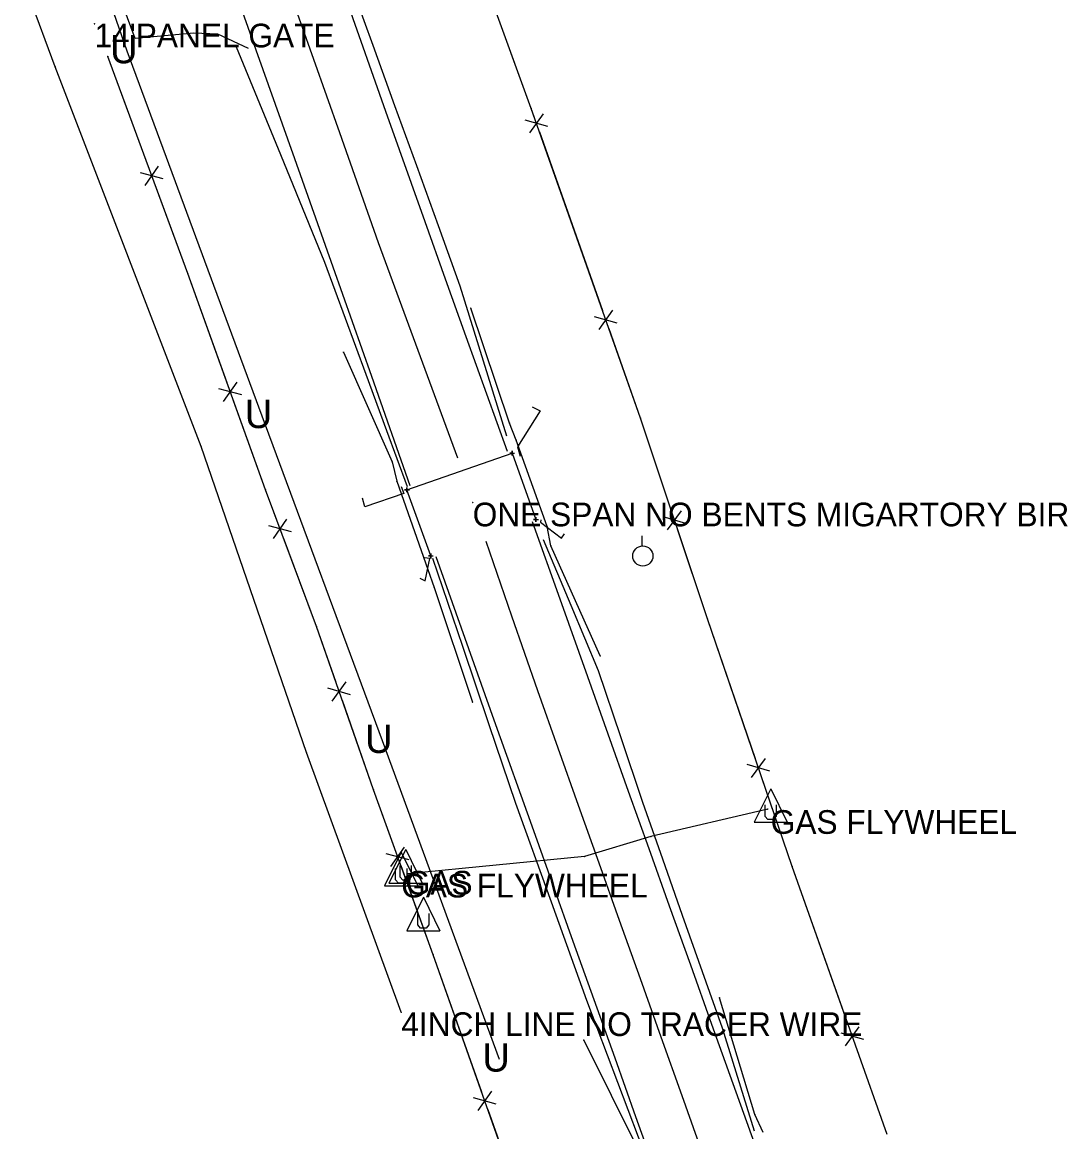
# Model space of a CAD drawing. Extents: x 1050807 to 1053552, y 395828 to 398415.
# Drawn here: x 1052358.5 to 1052579.3, y 396632.8 to 396867.1 of the extents above; entities that cross this region are included whole.
import ezdxf

# ---------------------------------------------------------------- set-up
doc = ezdxf.new("R2010")
doc.units = 0
for name, color, linetype in [('Default', 7, 'Continuous'), ('S_BRIDGE', 7, 'Continuous'), ('S_DRIVEWAY', 7, 'Continuous'), ('S_EDGE_CONCRETE', 7, 'Continuous'), ('S_EDGE_PAVEMENT', 7, 'Continuous'), ('S_FENCE', 7, 'Continuous'), ('S_GAS_UTILITIES', 7, 'Continuous'), ('S_GUARDRAIL', 7, 'Continuous'), ('S_MSC_PT_SYM', 7, 'Continuous'), ('S_PAVEMENT_CROWN', 7, 'Continuous'), ('S_RDW_PT_SYM', 7, 'Continuous'), ('S_SHOULDER', 7, 'Continuous'), ('S_STR_PT_SYM', 7, 'Continuous'), ('S_SURVEY_TEXT_ANNOT', 7, 'Continuous'), ('S_UNDERGROUND_CABLE', 7, 'Continuous'), ('S_UTILITY_POLE', 7, 'Continuous'), ('S_UTILITY_POLE_ANNOT', 7, 'Continuous'), ('S_UTL_PT_SYM', 7, 'Continuous'), ('S_WATER_UTILITIES', 7, 'Continuous'), ('S_WATER_UTILITIES_ANNOT', 7, 'Continuous')]:
    doc.layers.add(name, color=color, linetype=linetype)

msp = doc.modelspace()

# ---------------------------------------------------------------- linework, layer by layer
at = {"layer": 'S_BRIDGE'}
for p, q in [((1052439.78, 396768.34), (1052462.01, 396776.09)), ((1052462.01, 396776.09), (1052467.01, 396762.11)), ((1052444.83, 396754.39), (1052439.78, 396768.34))]:
    msp.add_line(p, q, dxfattribs=at)
at = {"layer": 'S_DRIVEWAY'}
msp.add_lwpolyline([(1052406.35, 396861.47), (1052399.84, 396864.53), (1052394.81, 396864.76), (1052382.42, 396863.64), (1052378.24, 396874.85), (1052383.77, 396877.82), (1052391.56, 396884.45), (1052395.94, 396888.79)], dxfattribs=at)
at = {"layer": 'S_EDGE_CONCRETE'}
for points in [[(1052466.22, 396785.86), (1052467.92, 396785.05), (1052463.09, 396777.45), (1052463.66, 396775.47)], [(1052438.55, 396769.02), (1052439.14, 396767.59), (1052430.89, 396764.79), (1052430.41, 396766.58)], [(1052468.01, 396762.05), (1052468, 396761.53), (1052472.4, 396758.14), (1052473.05, 396759.08)], [(1052442.5, 396749.68), (1052443.6, 396749.14), (1052444.62, 396753.83), (1052443.49, 396753.98)]]:
    msp.add_lwpolyline(points, dxfattribs=at)
at = {"layer": 'S_EDGE_PAVEMENT'}
for points in [[(1052460.97, 396776.43), (1052456.62, 396788.55), (1052452.28, 396800.67), (1052447.93, 396812.79), (1052443.59, 396824.9), (1052435.34, 396848.24), (1052427.09, 396871.57), (1052422.4, 396884.33), (1052417.71, 396897.09), (1052413.02, 396909.86), (1052408.33, 396922.62), (1052403.21, 396936.38), (1052398.09, 396950.14), (1052392.97, 396963.89), (1052387.86, 396977.65)], [(1052440.47, 396769.17), (1052432.33, 396792.24), (1052424.18, 396815.32), (1052416.08, 396838.25), (1052407.97, 396861.18), (1052400.04, 396883.52), (1052392.11, 396905.86), (1052386.39, 396922.34), (1052380.67, 396938.83), (1052374.95, 396955.32), (1052369.23, 396971.8)], [(1052513.12, 396630.45), (1052508.63, 396642.96), (1052504.15, 396655.48), (1052499.67, 396667.99), (1052495.19, 396680.5), (1052490.88, 396692.59), (1052486.56, 396704.68), (1052482.25, 396716.78), (1052477.94, 396728.87), (1052472.12, 396745.25), (1052466.29, 396761.63)], [(1052492.52, 396623.71), (1052488.11, 396636.03), (1052483.7, 396648.36), (1052479.29, 396660.69), (1052474.88, 396673.01), (1052466.54, 396696.37), (1052458.19, 396719.73), (1052452.07, 396736.99), (1052445.94, 396754.24)]]:
    msp.add_lwpolyline(points, dxfattribs=at)
at = {"layer": 'S_FENCE'}
for p, q in [((1052466.02, 396848.87), (1052444.41, 396908.05)), ((1052393.51, 396813.99), (1052376.64, 396859.85)), ((1052465.68, 396843.67), (1052468.59, 396847.74)), ((1052465.68, 396843.67), (1052468.59, 396847.74)), ((1052489.1, 396783.48), (1052466.02, 396848.87)), ((1052469.54, 396845.03), (1052464.73, 396846.37)), ((1052469.54, 396845.03), (1052464.73, 396846.37)), ((1052384.49, 396832.58), (1052387.34, 396836.69)), ((1052384.49, 396832.58), (1052387.34, 396836.69)), ((1052388.33, 396834), (1052383.5, 396835.28)), ((1052388.33, 396834), (1052383.5, 396835.28)), ((1052409.94, 396768.35), (1052393.51, 396813.99)), ((1052480.32, 396802.19), (1052483.23, 396806.26)), ((1052480.32, 396802.19), (1052483.23, 396806.26)), ((1052484.18, 396803.55), (1052479.37, 396804.89)), ((1052484.18, 396803.55), (1052479.37, 396804.89)), ((1052404.9, 396788.39), (1052400.08, 396789.7)), ((1052404.9, 396788.39), (1052400.08, 396789.7)), ((1052401.05, 396787), (1052403.93, 396791.09)), ((1052401.05, 396787), (1052403.93, 396791.09)), ((1052503.21, 396741.1), (1052489.1, 396783.48)), ((1052420.68, 396739.54), (1052409.94, 396768.35)), ((1052494.78, 396759.94), (1052497.76, 396763.95)), ((1052494.78, 396759.94), (1052497.76, 396763.95)), ((1052411.59, 396758.05), (1052414.43, 396762.16)), ((1052411.59, 396758.05), (1052414.43, 396762.16)), ((1052498.66, 396761.23), (1052493.87, 396762.66)), ((1052498.66, 396761.23), (1052493.87, 396762.66)), ((1052415.43, 396759.48), (1052410.59, 396760.73)), ((1052415.43, 396759.48), (1052410.59, 396760.73)), ((1052521.09, 396688.84), (1052503.21, 396741.1)), ((1052432.72, 396705.02), (1052420.68, 396739.54)), ((1052427.88, 396725.1), (1052423.07, 396726.46)), ((1052427.88, 396725.1), (1052423.07, 396726.46)), ((1052424.02, 396723.75), (1052426.94, 396727.81)), ((1052424.02, 396723.75), (1052426.94, 396727.81)), ((1052516.37, 396708.96), (1052511.57, 396710.35)), ((1052516.37, 396708.96), (1052511.57, 396710.35)), ((1052512.5, 396707.63), (1052515.44, 396711.67)), ((1052512.5, 396707.63), (1052515.44, 396711.67)), ((1052445.33, 396670.2), (1052432.72, 396705.02)), ((1052440.25, 396690.24), (1052435.42, 396691.54)), ((1052440.25, 396690.24), (1052435.42, 396691.54)), ((1052436.4, 396688.84), (1052439.28, 396692.93)), ((1052436.4, 396688.84), (1052439.28, 396692.93)), ((1052541.18, 396632.28), (1052521.09, 396688.84)), ((1052463.57, 396618.62), (1052445.33, 396670.2)), ((1052536.23, 396652.34), (1052531.41, 396653.67)), ((1052536.23, 396652.34), (1052531.41, 396653.67)), ((1052532.37, 396650.97), (1052535.27, 396655.04)), ((1052532.37, 396650.97), (1052535.27, 396655.04)), ((1052458.64, 396638.69), (1052453.83, 396640.03)), ((1052458.64, 396638.69), (1052453.83, 396640.03)), ((1052454.78, 396637.33), (1052457.69, 396641.4)), ((1052454.78, 396637.33), (1052457.69, 396641.4))]:
    msp.add_line(p, q, dxfattribs=at)
for points in [[(1052466.02, 396848.87), (1052459.17, 396867.63)], [(1052466.02, 396848.87), (1052459.17, 396867.63)], [(1052385.22, 396836.51), (1052376.64, 396859.85)], [(1052385.22, 396836.51), (1052376.64, 396859.85)], [(1052466.66, 396847.05), (1052466.02, 396848.87)], [(1052466.66, 396847.05), (1052466.02, 396848.87)], [(1052481.11, 396806.11), (1052467.8, 396843.82)], [(1052481.11, 396806.11), (1052467.8, 396843.82)], [(1052393.51, 396813.99), (1052386.6, 396832.76)], [(1052393.51, 396813.99), (1052386.6, 396832.76)], [(1052401.81, 396790.93), (1052393.51, 396813.99)], [(1052401.81, 396790.93), (1052393.51, 396813.99)], [(1052489.1, 396783.48), (1052482.44, 396802.34)], [(1052489.1, 396783.48), (1052482.44, 396802.34)], [(1052409.94, 396768.35), (1052403.17, 396787.17)], [(1052409.94, 396768.35), (1052403.17, 396787.17)], [(1052495.64, 396763.84), (1052489.1, 396783.48)], [(1052495.64, 396763.84), (1052489.1, 396783.48)], [(1052412.32, 396761.98), (1052409.94, 396768.35)], [(1052412.32, 396761.98), (1052409.94, 396768.35)], [(1052503.21, 396741.1), (1052496.9, 396760.05)], [(1052503.21, 396741.1), (1052496.9, 396760.05)], [(1052420.68, 396739.54), (1052413.71, 396758.24)], [(1052420.68, 396739.54), (1052413.71, 396758.24)], [(1052513.32, 396711.54), (1052503.21, 396741.1)], [(1052513.32, 396711.54), (1052503.21, 396741.1)], [(1052424.82, 396727.66), (1052420.68, 396739.54)], [(1052424.82, 396727.66), (1052420.68, 396739.54)], [(1052432.72, 396705.02), (1052426.14, 396723.89)], [(1052432.72, 396705.02), (1052426.14, 396723.89)], [(1052521.09, 396688.84), (1052514.62, 396707.76)], [(1052521.09, 396688.84), (1052514.62, 396707.76)], [(1052437.16, 396692.77), (1052432.72, 396705.02)], [(1052437.16, 396692.77), (1052432.72, 396705.02)], [(1052445.33, 396670.2), (1052438.52, 396689.01)], [(1052445.33, 396670.2), (1052438.52, 396689.01)], [(1052533.15, 396654.89), (1052521.09, 396688.84)], [(1052533.15, 396654.89), (1052521.09, 396688.84)], [(1052455.57, 396641.25), (1052445.33, 396670.2)], [(1052455.57, 396641.25), (1052445.33, 396670.2)], [(1052541.18, 396632.28), (1052534.49, 396651.12)], [(1052541.18, 396632.28), (1052534.49, 396651.12)], [(1052463.57, 396618.62), (1052456.9, 396637.48)], [(1052463.57, 396618.62), (1052456.9, 396637.48)]]:
    msp.add_lwpolyline(points, dxfattribs=at)
at = {"layer": 'S_GAS_UTILITIES'}
for p, q in [((1052515.94, 396700.98), (1052491.29, 396695.18)), ((1052491.29, 396695.18), (1052477.28, 396690.97)), ((1052477.28, 396690.97), (1052439.99, 396687.31))]:
    msp.add_line(p, q, dxfattribs=at)
at = {"layer": 'S_GUARDRAIL'}
for p, q in [((1052461.41, 396782.43), (1052453.25, 396806.67)), ((1052426.4, 396797.4), (1052436.67, 396774.26)), ((1052462.81, 396778.82), (1052461.41, 396782.43)), ((1052469.38, 396760.59), (1052462.81, 396778.82)), ((1052436.67, 396774.26), (1052437.67, 396770.15)), ((1052437.67, 396770.15), (1052444.15, 396751.54)), ((1052470.12, 396756.54), (1052469.38, 396760.59)), ((1052480.58, 396733.28), (1052470.12, 396756.54)), ((1052444.15, 396751.54), (1052445.5, 396747.77)), ((1052445.5, 396747.77), (1052453.64, 396723.56)), ((1052513.23, 396636.52), (1052505.73, 396661.12)), ((1052477.08, 396652.19), (1052488.66, 396628.95)), ((1052514.96, 396632.69), (1052513.23, 396636.52))]:
    msp.add_line(p, q, dxfattribs=at)
at = {"layer": 'S_MSC_PT_SYM'}
for points in [[(1052373.81, 396866.74), (1052373.81, 396866.79), (1052373.81, 396866.74), (1052373.76, 396866.74), (1052373.81, 396866.74), (1052373.81, 396866.69), (1052373.81, 396866.74), (1052373.86, 396866.74)], [(1052376.64, 396859.85), (1052376.64, 396859.9), (1052376.64, 396859.85), (1052376.59, 396859.85), (1052376.64, 396859.85), (1052376.64, 396859.8), (1052376.64, 396859.85), (1052376.69, 396859.85)], [(1052466.02, 396848.87), (1052466.02, 396848.92), (1052466.02, 396848.87), (1052465.97, 396848.87), (1052466.02, 396848.87), (1052466.02, 396848.82), (1052466.02, 396848.87), (1052466.07, 396848.87)], [(1052393.51, 396813.99), (1052393.51, 396814.04), (1052393.51, 396813.99), (1052393.46, 396813.99), (1052393.51, 396813.99), (1052393.51, 396813.94), (1052393.51, 396813.99), (1052393.56, 396813.99)], [(1052489.1, 396783.48), (1052489.1, 396783.53), (1052489.1, 396783.48), (1052489.05, 396783.48), (1052489.1, 396783.48), (1052489.1, 396783.43), (1052489.1, 396783.48), (1052489.15, 396783.48)], [(1052409.94, 396768.35), (1052409.94, 396768.4), (1052409.94, 396768.35), (1052409.89, 396768.35), (1052409.94, 396768.35), (1052409.94, 396768.3), (1052409.94, 396768.35), (1052409.99, 396768.35)], [(1052453.65, 396765.65), (1052453.65, 396765.7), (1052453.65, 396765.65), (1052453.6, 396765.65), (1052453.65, 396765.65), (1052453.65, 396765.6), (1052453.65, 396765.65), (1052453.7, 396765.65)], [(1052503.21, 396741.1), (1052503.21, 396741.15), (1052503.21, 396741.1), (1052503.16, 396741.1), (1052503.21, 396741.1), (1052503.21, 396741.05), (1052503.21, 396741.1), (1052503.26, 396741.1)], [(1052420.68, 396739.54), (1052420.68, 396739.59), (1052420.68, 396739.54), (1052420.63, 396739.54), (1052420.68, 396739.54), (1052420.68, 396739.49), (1052420.68, 396739.54), (1052420.73, 396739.54)], [(1052432.72, 396705.02), (1052432.72, 396705.07), (1052432.72, 396705.02), (1052432.67, 396705.02), (1052432.72, 396705.02), (1052432.72, 396704.97), (1052432.72, 396705.02), (1052432.77, 396705.02)], [(1052521.09, 396688.84), (1052521.09, 396688.89), (1052521.09, 396688.84), (1052521.04, 396688.84), (1052521.09, 396688.84), (1052521.09, 396688.79), (1052521.09, 396688.84), (1052521.14, 396688.84)], [(1052445.33, 396670.2), (1052445.33, 396670.25), (1052445.33, 396670.2), (1052445.28, 396670.2), (1052445.33, 396670.2), (1052445.33, 396670.15), (1052445.33, 396670.2), (1052445.38, 396670.2)]]:
    msp.add_lwpolyline(points, dxfattribs=at)
at = {"layer": 'S_PAVEMENT_CROWN'}
for points in [[(1052450.54, 396775.06), (1052442.17, 396797.78), (1052433.8, 396820.49), (1052425.59, 396843.69), (1052417.38, 396866.9), (1052412.95, 396879.4), (1052408.53, 396891.91), (1052404.1, 396904.42), (1052399.68, 396916.93), (1052391.71, 396939.22), (1052383.74, 396961.52), (1052378.98, 396974.84)], [(1052502.26, 396628.13), (1052497.86, 396640.46), (1052493.46, 396652.79), (1052489.06, 396665.12), (1052484.66, 396677.44), (1052480.34, 396689.57), (1052476.02, 396701.7), (1052471.71, 396713.83), (1052467.39, 396725.96), (1052461.95, 396741.7), (1052456.52, 396757.45)]]:
    msp.add_lwpolyline(points, dxfattribs=at)
at = {"layer": 'S_RDW_PT_SYM'}
for points in [[(1052453.25, 396806.67), (1052453.25, 396806.72), (1052453.25, 396806.67), (1052453.2, 396806.67), (1052453.25, 396806.67), (1052453.25, 396806.62), (1052453.25, 396806.67), (1052453.3, 396806.67)], [(1052426.4, 396797.4), (1052426.4, 396797.45), (1052426.4, 396797.4), (1052426.35, 396797.4), (1052426.4, 396797.4), (1052426.4, 396797.35), (1052426.4, 396797.4), (1052426.45, 396797.4)], [(1052461.41, 396782.43), (1052461.41, 396782.48), (1052461.41, 396782.43), (1052461.36, 396782.43), (1052461.41, 396782.43), (1052461.41, 396782.38), (1052461.41, 396782.43), (1052461.46, 396782.43)], [(1052462.81, 396778.82), (1052462.81, 396778.87), (1052462.81, 396778.82), (1052462.76, 396778.82), (1052462.81, 396778.82), (1052462.81, 396778.77), (1052462.81, 396778.82), (1052462.86, 396778.82)], [(1052436.67, 396774.26), (1052436.67, 396774.31), (1052436.67, 396774.26), (1052436.62, 396774.26), (1052436.67, 396774.26), (1052436.67, 396774.21), (1052436.67, 396774.26), (1052436.72, 396774.26)], [(1052437.67, 396770.15), (1052437.67, 396770.2), (1052437.67, 396770.15), (1052437.62, 396770.15), (1052437.67, 396770.15), (1052437.67, 396770.1), (1052437.67, 396770.15), (1052437.72, 396770.15)], [(1052469.38, 396760.59), (1052469.38, 396760.64), (1052469.38, 396760.59), (1052469.33, 396760.59), (1052469.38, 396760.59), (1052469.38, 396760.54), (1052469.38, 396760.59), (1052469.43, 396760.59)], [(1052470.12, 396756.54), (1052470.12, 396756.59), (1052470.12, 396756.54), (1052470.07, 396756.54), (1052470.12, 396756.54), (1052470.12, 396756.49), (1052470.12, 396756.54), (1052470.18, 396756.54)], [(1052444.15, 396751.54), (1052444.15, 396751.59), (1052444.15, 396751.54), (1052444.1, 396751.54), (1052444.15, 396751.54), (1052444.15, 396751.49), (1052444.15, 396751.54), (1052444.2, 396751.54)], [(1052445.5, 396747.77), (1052445.5, 396747.82), (1052445.5, 396747.77), (1052445.45, 396747.77), (1052445.5, 396747.77), (1052445.5, 396747.72), (1052445.5, 396747.77), (1052445.55, 396747.77)], [(1052480.58, 396733.28), (1052480.58, 396733.33), (1052480.58, 396733.28), (1052480.53, 396733.28), (1052480.58, 396733.28), (1052480.58, 396733.23), (1052480.58, 396733.28), (1052480.63, 396733.28)], [(1052453.64, 396723.56), (1052453.64, 396723.61), (1052453.64, 396723.56), (1052453.59, 396723.56), (1052453.64, 396723.56), (1052453.64, 396723.51), (1052453.64, 396723.56), (1052453.69, 396723.56)], [(1052505.73, 396661.12), (1052505.73, 396661.17), (1052505.73, 396661.12), (1052505.68, 396661.12), (1052505.73, 396661.12), (1052505.73, 396661.07), (1052505.73, 396661.12), (1052505.78, 396661.12)], [(1052477.08, 396652.19), (1052477.08, 396652.24), (1052477.08, 396652.19), (1052477.03, 396652.19), (1052477.08, 396652.19), (1052477.08, 396652.14), (1052477.08, 396652.19), (1052477.13, 396652.19)], [(1052513.23, 396636.52), (1052513.23, 396636.57), (1052513.23, 396636.52), (1052513.18, 396636.52), (1052513.23, 396636.52), (1052513.23, 396636.47), (1052513.23, 396636.52), (1052513.28, 396636.52)]]:
    msp.add_lwpolyline(points, dxfattribs=at)
at = {"layer": 'S_SHOULDER'}
for points in [[(1052460.83, 396779.67), (1052455.93, 396795.51), (1052451.02, 396811.34), (1052446.43, 396824.04), (1052441.84, 396836.73), (1052437.25, 396849.42), (1052432.65, 396862.11), (1052426.93, 396877.84), (1052421.22, 396893.57)], [(1052439.89, 396768.99), (1052435.53, 396780.83), (1052431.17, 396792.67), (1052426.81, 396804.51), (1052422.45, 396816.35), (1052413.13, 396839.07), (1052403.81, 396861.8)], [(1052513.13, 396632.96), (1052506.36, 396654.73), (1052502.16, 396666.63), (1052497.96, 396678.53), (1052493.76, 396690.43), (1052489.56, 396702.33), (1052484.9, 396716.24), (1052480.23, 396730.16), (1052474.42, 396743.96), (1052468.61, 396757.77)], [(1052490.84, 396625.96), (1052484.29, 396643.25), (1052477.73, 396660.54), (1052470.26, 396681.35), (1052462.79, 396702.15), (1052457.16, 396718.73), (1052451.54, 396735.31), (1052445.27, 396753.86)]]:
    msp.add_lwpolyline(points, dxfattribs=at)
at = {"layer": 'S_STR_PT_SYM'}
for points in [[(1052462.01, 396776.09), (1052462.01, 396776.59), (1052462.01, 396776.09), (1052461.51, 396776.09), (1052462.01, 396776.09), (1052462.01, 396775.59), (1052462.01, 396776.09), (1052462.51, 396776.09)], [(1052439.78, 396768.34), (1052439.78, 396768.84), (1052439.78, 396768.34), (1052439.28, 396768.34), (1052439.78, 396768.34), (1052439.78, 396767.84), (1052439.78, 396768.34), (1052440.28, 396768.34)], [(1052467.01, 396762.11), (1052467.01, 396762.61), (1052467.01, 396762.11), (1052466.51, 396762.11), (1052467.01, 396762.11), (1052467.01, 396761.61), (1052467.01, 396762.11), (1052467.51, 396762.11)], [(1052444.83, 396754.39), (1052444.83, 396754.89), (1052444.83, 396754.39), (1052444.33, 396754.39), (1052444.83, 396754.39), (1052444.83, 396753.89), (1052444.83, 396754.39), (1052445.33, 396754.39)]]:
    msp.add_lwpolyline(points, dxfattribs=at)
at = {"layer": 'S_UNDERGROUND_CABLE'}
for p, q in [((1052380.74, 396860.92), (1052359.09, 396922.53)), ((1052409.18, 396783.92), (1052380.74, 396860.92)), ((1052434.58, 396715.35), (1052409.18, 396783.92)), ((1052459.33, 396648.09), (1052434.58, 396715.35)), ((1052516.56, 396705.27), (1052513.04, 396698.18)), ((1052516.56, 396705.27), (1052520.05, 396698.18)), ((1052515.36, 396699.42), (1052515.36, 396701.86)), ((1052517.73, 396701.86), (1052517.73, 396699.42)), ((1052513.04, 396698.18), (1052520.05, 396698.18)), ((1052515.98, 396698.76), (1052515.36, 396699.42)), ((1052517.18, 396698.76), (1052515.98, 396698.76)), ((1052517.73, 396699.42), (1052517.18, 396698.76)), ((1052438.56, 396691.85), (1052435.04, 396684.76)), ((1052439.51, 396692.45), (1052435.98, 396685.36)), ((1052438.56, 396691.85), (1052442.05, 396684.76)), ((1052439.51, 396692.45), (1052443, 396685.36)), ((1052437.36, 396686), (1052437.36, 396688.44)), ((1052438.31, 396686.6), (1052438.31, 396689.04)), ((1052439.72, 396688.44), (1052439.72, 396686)), ((1052440.67, 396689.04), (1052440.67, 396686.6)), ((1052438.93, 396685.94), (1052438.31, 396686.6)), ((1052440.67, 396686.6), (1052440.13, 396685.94)), ((1052435.04, 396684.76), (1052442.05, 396684.76)), ((1052435.98, 396685.36), (1052443, 396685.36)), ((1052437.98, 396685.34), (1052437.36, 396686)), ((1052439.18, 396685.34), (1052437.98, 396685.34)), ((1052440.13, 396685.94), (1052438.93, 396685.94)), ((1052439.72, 396686), (1052439.18, 396685.34)), ((1052443.24, 396682.37), (1052439.72, 396675.28)), ((1052443.24, 396682.37), (1052446.73, 396675.28)), ((1052442.04, 396676.52), (1052442.04, 396678.96)), ((1052444.41, 396678.96), (1052444.41, 396676.52)), ((1052439.72, 396675.28), (1052446.73, 396675.28)), ((1052442.66, 396675.86), (1052442.04, 396676.52)), ((1052443.86, 396675.86), (1052442.66, 396675.86)), ((1052444.41, 396676.52), (1052443.86, 396675.86))]:
    msp.add_line(p, q, dxfattribs=at)
at = {"layer": 'S_UTILITY_POLE'}
msp.add_line((1052489.45, 396756.54), (1052489.45, 396758.64), dxfattribs=at)
msp.add_circle((1052489.57, 396754.39), 2.13, dxfattribs=at)
at = {"layer": 'S_UTL_PT_SYM'}
for points in [[(1052365.48, 396857.64), (1052365.48, 396857.69), (1052365.48, 396857.64), (1052365.43, 396857.64), (1052365.48, 396857.64), (1052365.48, 396857.59), (1052365.48, 396857.64), (1052365.53, 396857.64)], [(1052396.34, 396777.48), (1052396.34, 396777.53), (1052396.34, 396777.48), (1052396.29, 396777.48), (1052396.34, 396777.48), (1052396.34, 396777.43), (1052396.34, 396777.48), (1052396.39, 396777.48)], [(1052418.55, 396712.88), (1052418.55, 396712.93), (1052418.55, 396712.88), (1052418.5, 396712.88), (1052418.55, 396712.88), (1052418.55, 396712.83), (1052418.55, 396712.88), (1052418.6, 396712.88)], [(1052515.94, 396700.98), (1052515.94, 396701.03), (1052515.94, 396700.98), (1052515.89, 396700.98), (1052515.94, 396700.98), (1052515.94, 396700.93), (1052515.94, 396700.98), (1052515.99, 396700.98)], [(1052491.29, 396695.18), (1052491.29, 396695.23), (1052491.29, 396695.18), (1052491.24, 396695.18), (1052491.29, 396695.18), (1052491.29, 396695.13), (1052491.29, 396695.18), (1052491.34, 396695.18)], [(1052477.28, 396690.97), (1052477.28, 396691.02), (1052477.28, 396690.97), (1052477.23, 396690.97), (1052477.28, 396690.97), (1052477.28, 396690.92), (1052477.28, 396690.97), (1052477.33, 396690.97)], [(1052439.99, 396687.31), (1052439.99, 396687.36), (1052439.99, 396687.31), (1052439.94, 396687.31), (1052439.99, 396687.31), (1052439.99, 396687.26), (1052439.99, 396687.31), (1052440.04, 396687.31)], [(1052438.58, 396658.07), (1052438.58, 396658.12), (1052438.58, 396658.07), (1052438.53, 396658.07), (1052438.58, 396658.07), (1052438.58, 396658.02), (1052438.58, 396658.07), (1052438.63, 396658.07)]]:
    msp.add_lwpolyline(points, dxfattribs=at)
at = {"layer": 'S_WATER_UTILITIES'}
for p, q in [((1052365.48, 396857.64), (1052334.35, 396941.99)), ((1052396.34, 396777.48), (1052365.48, 396857.64)), ((1052418.55, 396712.88), (1052396.34, 396777.48)), ((1052438.58, 396658.07), (1052418.55, 396712.88))]:
    msp.add_line(p, q, dxfattribs=at)

# ---------------------------------------------------------------- texts
at = {"layer": 'Default'}
for p in [(1052377.11, 396858.38), (1052405.55, 396781.38), (1052430.95, 396712.81), (1052455.7, 396645.55)]:
    msp.add_text('U', height=6, dxfattribs=at).set_placement(p)
at = {"layer": 'S_SURVEY_TEXT_ANNOT'}
for s, p in [("14'PANEL GATE", (1052373.81, 396861.74)), ('ONE SPAN NO BENTS MIGARTORY BIR', (1052453.65, 396760.65))]:
    msp.add_text(s, height=5, dxfattribs=at).set_placement(p)
at = {"layer": 'S_UTILITY_POLE_ANNOT'}
for s, p in [('GAS FLYWHEEL', (1052516.56, 396695.74)), ('GAS FLYWHEEL', (1052438.56, 396682.31)), ('GAS', (1052439.51, 396682.92))]:
    msp.add_text(s, height=5, dxfattribs=at).set_placement(p)
at = {"layer": 'S_WATER_UTILITIES_ANNOT'}
msp.add_text('4INCH LINE NO TRACER WIRE', height=5, dxfattribs=at).set_placement((1052438.58, 396653.07))

doc.saveas('drawing.dxf')
